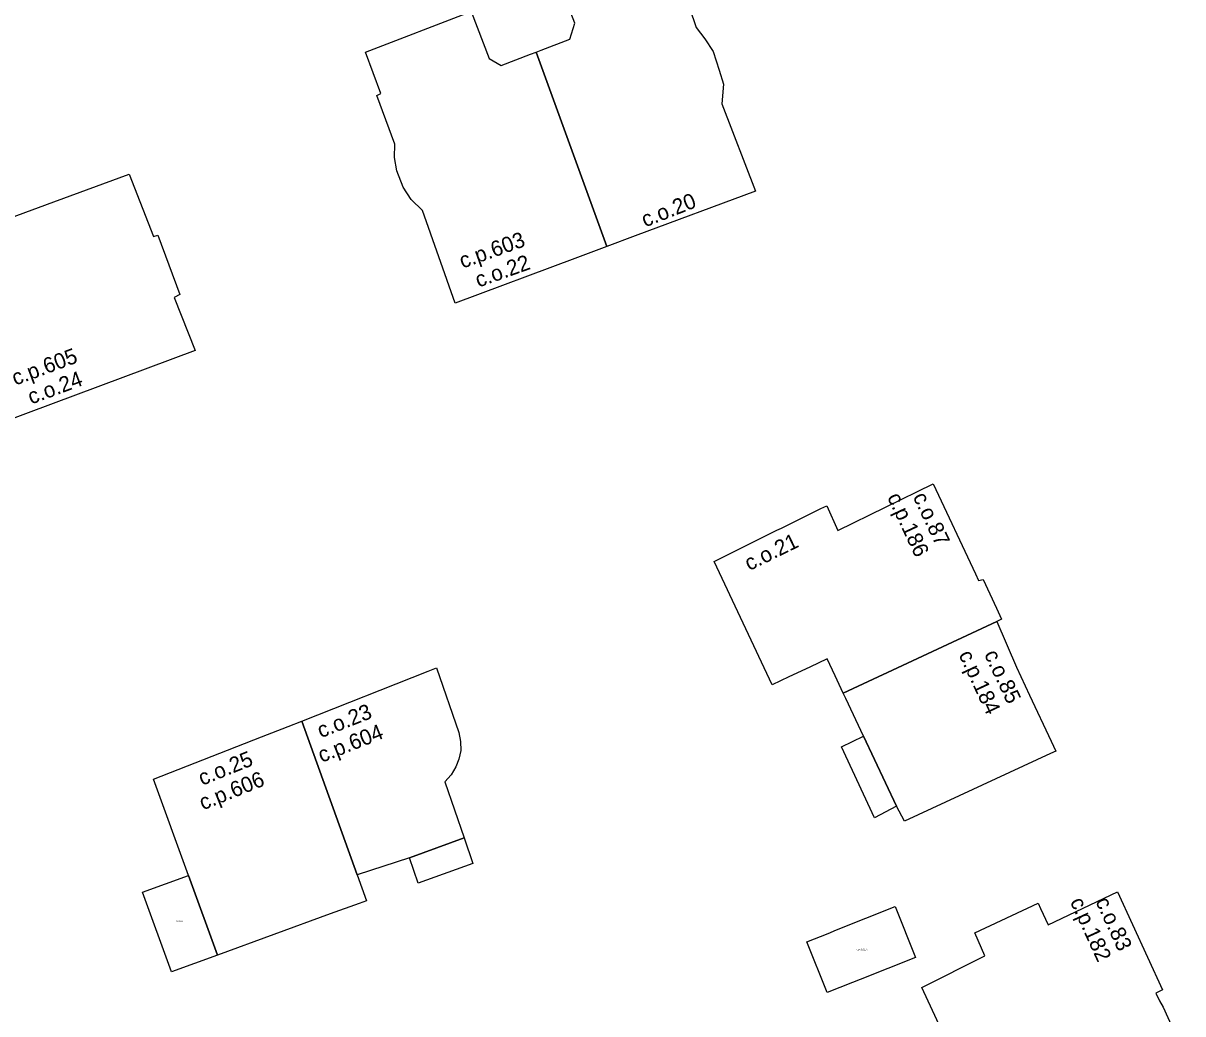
# Model space of a CAD drawing. Extents: x -600391 to -599491, y -1160176 to -1159402.
# Drawn here: x -600297.1 to -600222.1, y -1159718.1 to -1159654.1 of the extents above; entities that cross this region are included whole.
import ezdxf

# ---------------------------------------------------------------- set-up
doc = ezdxf.new("R2010")
doc.units = 0
for name, color, linetype in [('Level 10', 7, 'Continuous'), ('Level 12', 7, 'Continuous'), ('Level 24', 7, 'Continuous'), ('Level 25', 7, 'Continuous'), ('Level 61', 7, 'Continuous'), ('Level 62', 7, 'Continuous')]:
    doc.layers.add(name, color=color, linetype=linetype)

msp = doc.modelspace()

# ---------------------------------------------------------------- linework, layer by layer
at = {"layer": 'Level 61'}
for points in [[(-600261.4, -1159654.06), (-600262.51, -1159651.15)], [(-600254.41, -1159651.78), (-600253.55, -1159654.34)], [(-600274.92, -1159655.92), (-600268.09, -1159653.3)], [(-600268.09, -1159653.3), (-600266.93, -1159656.35)], [(-600261.71, -1159655.09), (-600261.4, -1159654.06)], [(-600253.55, -1159654.34), (-600252.98, -1159655.06)], [(-600263.57, -1159655.8), (-600261.71, -1159655.09)], [(-600252.98, -1159655.06), (-600252.44, -1159655.89)], [(-600273.93, -1159658.6), (-600274.92, -1159655.92)], [(-600266.93, -1159656.35), (-600266.16, -1159656.79)], [(-600266.16, -1159656.79), (-600264.26, -1159656.06)], [(-600264.26, -1159656.06), (-600263.9, -1159655.92)], [(-600263.9, -1159655.92), (-600263.57, -1159655.8)], [(-600259.33, -1159668.5), (-600263.9, -1159655.92)], [(-600263.9, -1159655.92), (-600259.33, -1159668.5)], [(-600252.44, -1159655.89), (-600252.06, -1159657.09)], [(-600252.06, -1159657.09), (-600251.78, -1159658)], [(-600274.19, -1159658.74), (-600273.93, -1159658.6)], [(-600251.78, -1159658), (-600251.89, -1159659.27)], [(-600273.02, -1159661.88), (-600274.19, -1159658.74)], [(-600251.89, -1159659.27), (-600249.71, -1159664.91)], [(-600273.06, -1159662.75), (-600273.02, -1159661.88)], [(-600272.91, -1159663.6), (-600273.06, -1159662.75)], [(-600295.07, -1159665.6), (-600290.21, -1159663.81)], [(-600290.21, -1159663.81), (-600288.63, -1159667.85)], [(-600272.49, -1159664.66), (-600272.91, -1159663.6)], [(-600271.98, -1159665.45), (-600272.49, -1159664.66)], [(-600249.71, -1159664.91), (-600257.5, -1159667.81)], [(-600297.47, -1159666.49), (-600295.07, -1159665.6)], [(-600271.23, -1159666.16), (-600271.98, -1159665.45)], [(-600269.13, -1159672.15), (-600271.23, -1159666.16)], [(-600288.63, -1159667.85), (-600288.34, -1159667.77)], [(-600288.34, -1159667.77), (-600286.92, -1159671.6)], [(-600257.5, -1159667.81), (-600259.33, -1159668.5)], [(-600259.33, -1159668.5), (-600261.39, -1159669.26)], [(-600261.39, -1159669.26), (-600269.13, -1159672.15)], [(-600286.92, -1159671.6), (-600287.29, -1159671.79)], [(-600287.29, -1159671.79), (-600285.93, -1159675.22)], [(-600285.93, -1159675.22), (-600298.35, -1159679.84)], [(-600244.4, -1159686.86), (-600238.23, -1159683.84)], [(-600238.23, -1159683.84), (-600235.49, -1159689.66)], [(-600248.04, -1159686.7), (-600245.49, -1159685.44)], [(-600245.49, -1159685.44), (-600245.1, -1159685.25)], [(-600245.1, -1159685.25), (-600244.4, -1159686.86)], [(-600252.39, -1159688.85), (-600248.34, -1159686.84)], [(-600248.34, -1159686.84), (-600248.04, -1159686.7)], [(-600248.64, -1159696.83), (-600252.39, -1159688.85)], [(-600235.49, -1159689.66), (-600235.29, -1159690.09)], [(-600235.29, -1159690.09), (-600235, -1159690.02)], [(-600235, -1159690.02), (-600234.14, -1159691.88)], [(-600234.14, -1159691.88), (-600233.82, -1159692.58)], [(-600244.04, -1159697.37), (-600234.11, -1159692.73)], [(-600234.11, -1159692.73), (-600244.04, -1159697.37)], [(-600233.82, -1159692.58), (-600234.11, -1159692.73)], [(-600234.11, -1159692.73), (-600232.84, -1159695.69)], [(-600245.09, -1159695.16), (-600246.2, -1159695.68)], [(-600244.57, -1159696.25), (-600245.09, -1159695.16)], [(-600279.05, -1159699.17), (-600270.87, -1159695.95)], [(-600270.87, -1159695.95), (-600270.33, -1159695.74)], [(-600270.33, -1159695.74), (-600268.9, -1159699.92)], [(-600246.2, -1159695.68), (-600247.55, -1159696.32)], [(-600232.84, -1159695.69), (-600231.99, -1159697.5)], [(-600247.55, -1159696.32), (-600248.64, -1159696.83)], [(-600244.04, -1159697.37), (-600244.57, -1159696.25)], [(-600243.88, -1159697.72), (-600244.04, -1159697.37)], [(-600231.99, -1159697.5), (-600230.6, -1159700.47)], [(-600242.73, -1159700.14), (-600243.88, -1159697.72)], [(-600281.65, -1159700.19), (-600279.93, -1159699.52)], [(-600279.93, -1159699.52), (-600279.05, -1159699.17)], [(-600275.47, -1159709.12), (-600279.05, -1159699.17)], [(-600279.05, -1159699.17), (-600275.47, -1159709.12)], [(-600288.64, -1159702.94), (-600281.65, -1159700.19)], [(-600268.9, -1159699.92), (-600268.78, -1159700.49)], [(-600268.78, -1159700.49), (-600268.77, -1159701.08)], [(-600244.15, -1159700.85), (-600242.73, -1159700.14)], [(-600242.73, -1159700.14), (-600240.59, -1159704.68)], [(-600240.59, -1159704.68), (-600242.73, -1159700.14)], [(-600230.6, -1159700.47), (-600230.3, -1159701.11)], [(-600268.77, -1159701.08), (-600268.89, -1159701.64)], [(-600242.01, -1159705.44), (-600244.15, -1159700.85)], [(-600230.65, -1159701.27), (-600240.09, -1159705.64)], [(-600230.3, -1159701.11), (-600230.65, -1159701.27)], [(-600269.08, -1159702.13), (-600269.39, -1159702.66)], [(-600268.89, -1159701.64), (-600269.08, -1159702.13)], [(-600269.39, -1159702.66), (-600269.79, -1159703.1)], [(-600286.37, -1159709.16), (-600288.64, -1159702.94)], [(-600269.79, -1159703.1), (-600268.55, -1159706.72)], [(-600240.59, -1159704.68), (-600242.01, -1159705.44)], [(-600240.09, -1159705.64), (-600240.59, -1159704.68)], [(-600268.55, -1159706.72), (-600272.09, -1159708.01)], [(-600272.09, -1159708.01), (-600268.55, -1159706.72)], [(-600268.55, -1159706.72), (-600267.98, -1159708.38)], [(-600272.09, -1159708.01), (-600275.47, -1159709.12)], [(-600271.52, -1159709.66), (-600272.09, -1159708.01)], [(-600267.98, -1159708.38), (-600271.52, -1159709.66)], [(-600289.33, -1159710.24), (-600286.37, -1159709.16)], [(-600284.49, -1159714.31), (-600286.37, -1159709.16)], [(-600286.37, -1159709.16), (-600284.49, -1159714.31)], [(-600275.47, -1159709.12), (-600274.87, -1159710.79)], [(-600287.46, -1159715.39), (-600289.33, -1159710.24)], [(-600230.8, -1159712.34), (-600226.31, -1159710.22)], [(-600226.31, -1159710.22), (-600223.41, -1159716.54)], [(-600275.34, -1159710.96), (-600277.2, -1159711.64)], [(-600274.87, -1159710.79), (-600275.34, -1159710.96)], [(-600235.53, -1159712.86), (-600231.44, -1159710.94)], [(-600231.44, -1159710.94), (-600231.28, -1159711.3)], [(-600277.2, -1159711.64), (-600284.49, -1159714.31)], [(-600244.48, -1159712.68), (-600240.68, -1159711.17)], [(-600240.68, -1159711.17), (-600239.37, -1159714.45)], [(-600231.28, -1159711.3), (-600230.8, -1159712.34)], [(-600246.39, -1159713.44), (-600245.02, -1159712.9)], [(-600245.02, -1159712.9), (-600244.48, -1159712.68)], [(-600234.89, -1159714.36), (-600235.53, -1159712.86)], [(-600245.08, -1159716.73), (-600246.39, -1159713.44)], [(-600284.49, -1159714.31), (-600287.46, -1159715.39)], [(-600239.37, -1159714.45), (-600242.94, -1159715.88)], [(-600238.95, -1159716.4), (-600234.89, -1159714.36)], [(-600243.45, -1159716.08), (-600245.08, -1159716.73)], [(-600242.94, -1159715.88), (-600243.45, -1159716.08)], [(-600236.32, -1159722.1), (-600238.95, -1159716.4)], [(-600223.41, -1159716.54), (-600223.83, -1159716.76)], [(-600223.83, -1159716.76), (-600223.59, -1159717.26)], [(-600223.59, -1159717.26), (-600223.37, -1159717.68)], [(-600223.37, -1159717.68), (-600222.25, -1159720.11)]]:
    msp.add_lwpolyline(points, dxfattribs=at)
at = {"layer": 'Level 62'}
for points in [[(-600263.57, -1159655.8), (-600261.71, -1159655.09), (-600261.4, -1159654.06), (-600262.51, -1159651.15), (-600258.35, -1159649.57), (-600255.49, -1159648.45), (-600255.32, -1159648.91), (-600255.59, -1159648.97), (-600255.48, -1159649.3), (-600254.57, -1159651.84), (-600254.41, -1159651.78), (-600253.55, -1159654.34), (-600252.98, -1159655.06), (-600252.44, -1159655.89), (-600252.06, -1159657.09), (-600251.78, -1159658), (-600251.89, -1159659.27), (-600249.71, -1159664.91), (-600257.5, -1159667.81), (-600259.33, -1159668.5), (-600263.9, -1159655.92), (-600263.57, -1159655.8)], [(-600268.09, -1159653.3), (-600266.93, -1159656.35), (-600266.16, -1159656.79), (-600264.26, -1159656.06), (-600263.9, -1159655.92), (-600259.33, -1159668.5), (-600261.39, -1159669.26), (-600269.13, -1159672.15), (-600271.23, -1159666.16), (-600271.98, -1159665.45), (-600272.49, -1159664.66), (-600272.91, -1159663.6), (-600273.06, -1159662.75), (-600273.02, -1159661.88), (-600274.19, -1159658.74), (-600273.93, -1159658.6), (-600274.92, -1159655.92), (-600268.09, -1159653.3)], [(-600301.33, -1159671.72), (-600301.99, -1159669.93), (-600302.11, -1159669.59), (-600302.54, -1159668.41), (-600297.47, -1159666.49), (-600295.07, -1159665.6), (-600290.21, -1159663.81), (-600288.63, -1159667.85), (-600288.34, -1159667.77), (-600286.92, -1159671.6), (-600287.29, -1159671.79), (-600285.93, -1159675.22), (-600298.35, -1159679.84), (-600299.72, -1159676.09), (-600300.08, -1159676.22), (-600301.38, -1159672.64), (-600301.04, -1159672.5), (-600301.21, -1159672.04), (-600301.33, -1159671.72)], [(-600246.2, -1159695.68), (-600247.55, -1159696.32), (-600248.64, -1159696.83), (-600252.39, -1159688.85), (-600248.34, -1159686.84), (-600248.04, -1159686.7), (-600245.49, -1159685.44), (-600245.1, -1159685.25), (-600244.4, -1159686.86), (-600238.23, -1159683.84), (-600235.49, -1159689.66), (-600235.29, -1159690.09), (-600235, -1159690.02), (-600234.14, -1159691.88), (-600233.82, -1159692.58), (-600234.11, -1159692.73), (-600244.04, -1159697.37), (-600244.57, -1159696.25), (-600245.09, -1159695.16), (-600246.2, -1159695.68)], [(-600232.84, -1159695.69), (-600231.99, -1159697.5), (-600230.6, -1159700.47), (-600230.3, -1159701.11), (-600230.65, -1159701.27), (-600240.09, -1159705.64), (-600240.59, -1159704.68), (-600242.73, -1159700.14), (-600243.88, -1159697.72), (-600244.04, -1159697.37), (-600234.11, -1159692.73), (-600232.84, -1159695.69)], [(-600275.47, -1159709.12), (-600279.05, -1159699.17), (-600270.87, -1159695.95), (-600270.33, -1159695.74), (-600268.9, -1159699.92), (-600268.78, -1159700.49), (-600268.77, -1159701.08), (-600268.89, -1159701.64), (-600269.08, -1159702.13), (-600269.39, -1159702.66), (-600269.79, -1159703.1), (-600268.55, -1159706.72), (-600272.09, -1159708.01), (-600275.47, -1159709.12)], [(-600275.47, -1159709.12), (-600274.87, -1159710.79), (-600275.34, -1159710.96), (-600277.2, -1159711.64), (-600284.49, -1159714.31), (-600286.37, -1159709.16), (-600288.64, -1159702.94), (-600281.65, -1159700.19), (-600279.93, -1159699.52), (-600279.05, -1159699.17), (-600275.47, -1159709.12)], [(-600242.73, -1159700.14), (-600240.59, -1159704.68), (-600242.01, -1159705.44), (-600244.15, -1159700.85), (-600242.73, -1159700.14)], [(-600268.55, -1159706.72), (-600267.98, -1159708.38), (-600271.52, -1159709.66), (-600272.09, -1159708.01), (-600268.55, -1159706.72)], [(-600284.49, -1159714.31), (-600287.46, -1159715.39), (-600289.33, -1159710.24), (-600286.37, -1159709.16), (-600284.49, -1159714.31)], [(-600231.44, -1159710.94), (-600231.28, -1159711.3), (-600230.8, -1159712.34), (-600226.31, -1159710.22), (-600223.41, -1159716.54), (-600223.83, -1159716.76), (-600223.59, -1159717.26), (-600223.37, -1159717.68), (-600222.25, -1159720.11), (-600222.09, -1159720.45), (-600232.65, -1159725.48), (-600234.46, -1159726.34), (-600235.19, -1159724.85), (-600236.81, -1159725.63), (-600237.97, -1159722.9), (-600236.32, -1159722.1), (-600238.95, -1159716.4), (-600234.89, -1159714.36), (-600235.53, -1159712.86), (-600231.44, -1159710.94)], [(-600243.45, -1159716.08), (-600245.08, -1159716.73), (-600246.39, -1159713.44), (-600245.02, -1159712.9), (-600244.48, -1159712.68), (-600240.68, -1159711.17), (-600239.37, -1159714.45), (-600242.94, -1159715.88), (-600243.45, -1159716.08)]]:
    msp.add_lwpolyline(points, dxfattribs=at)

# ---------------------------------------------------------------- texts
at = {"layer": 'Level 10'}
for s, rotation, p in [('c.o.20', 21.44393, (-600256.851, -1159667.26)), ('c.o.22', 19.66346, (-600267.622, -1159671.155)), ('c.o.24', 20.40114, (-600296.537, -1159678.716)), ('c.o.87', 295.20936, (-600239.56, -1159684.668)), ('c.o.21', 26.03977, (-600250.117, -1159689.481)), ('c.o.85', 295.10689, (-600234.952, -1159694.848)), ('c.o.23', 21.59287, (-600277.81, -1159700.288)), ('c.o.25', 21.95036, (-600285.488, -1159703.361)), ('c.o.83', 294.65069, (-600227.757, -1159710.826))]:
    msp.add_text(s, height=1, rotation=rotation, dxfattribs=at).set_placement(p)
at = {"layer": 'Level 12'}
for s, rotation, p in [('c.p.603', 19.66346, (-600268.651, -1159669.926)), ('c.p.605', 20.40114, (-600297.568, -1159677.493)), ('c.p.186', 295.20936, (-600241.222, -1159684.693)), ('c.p.184', 295.10689, (-600236.601, -1159694.878)), ('c.p.604', 21.59287, (-600277.761, -1159701.876)), ('c.p.606', 21.95036, (-600285.434, -1159704.949)), ('c.p.182', 294.65069, (-600229.401, -1159710.843))]:
    msp.add_text(s, height=1, rotation=rotation, dxfattribs=at).set_placement(p)
at = {"layer": 'Level 24'}
msp.add_text('c.z.312', height=0.1, dxfattribs=at).set_placement((-600287.189, -1159712.157))
at = {"layer": 'Level 25'}
msp.add_text('c.pp.182_A', height=0.1, dxfattribs=at).set_placement((-600243.183, -1159713.987))

doc.saveas('drawing.dxf')
